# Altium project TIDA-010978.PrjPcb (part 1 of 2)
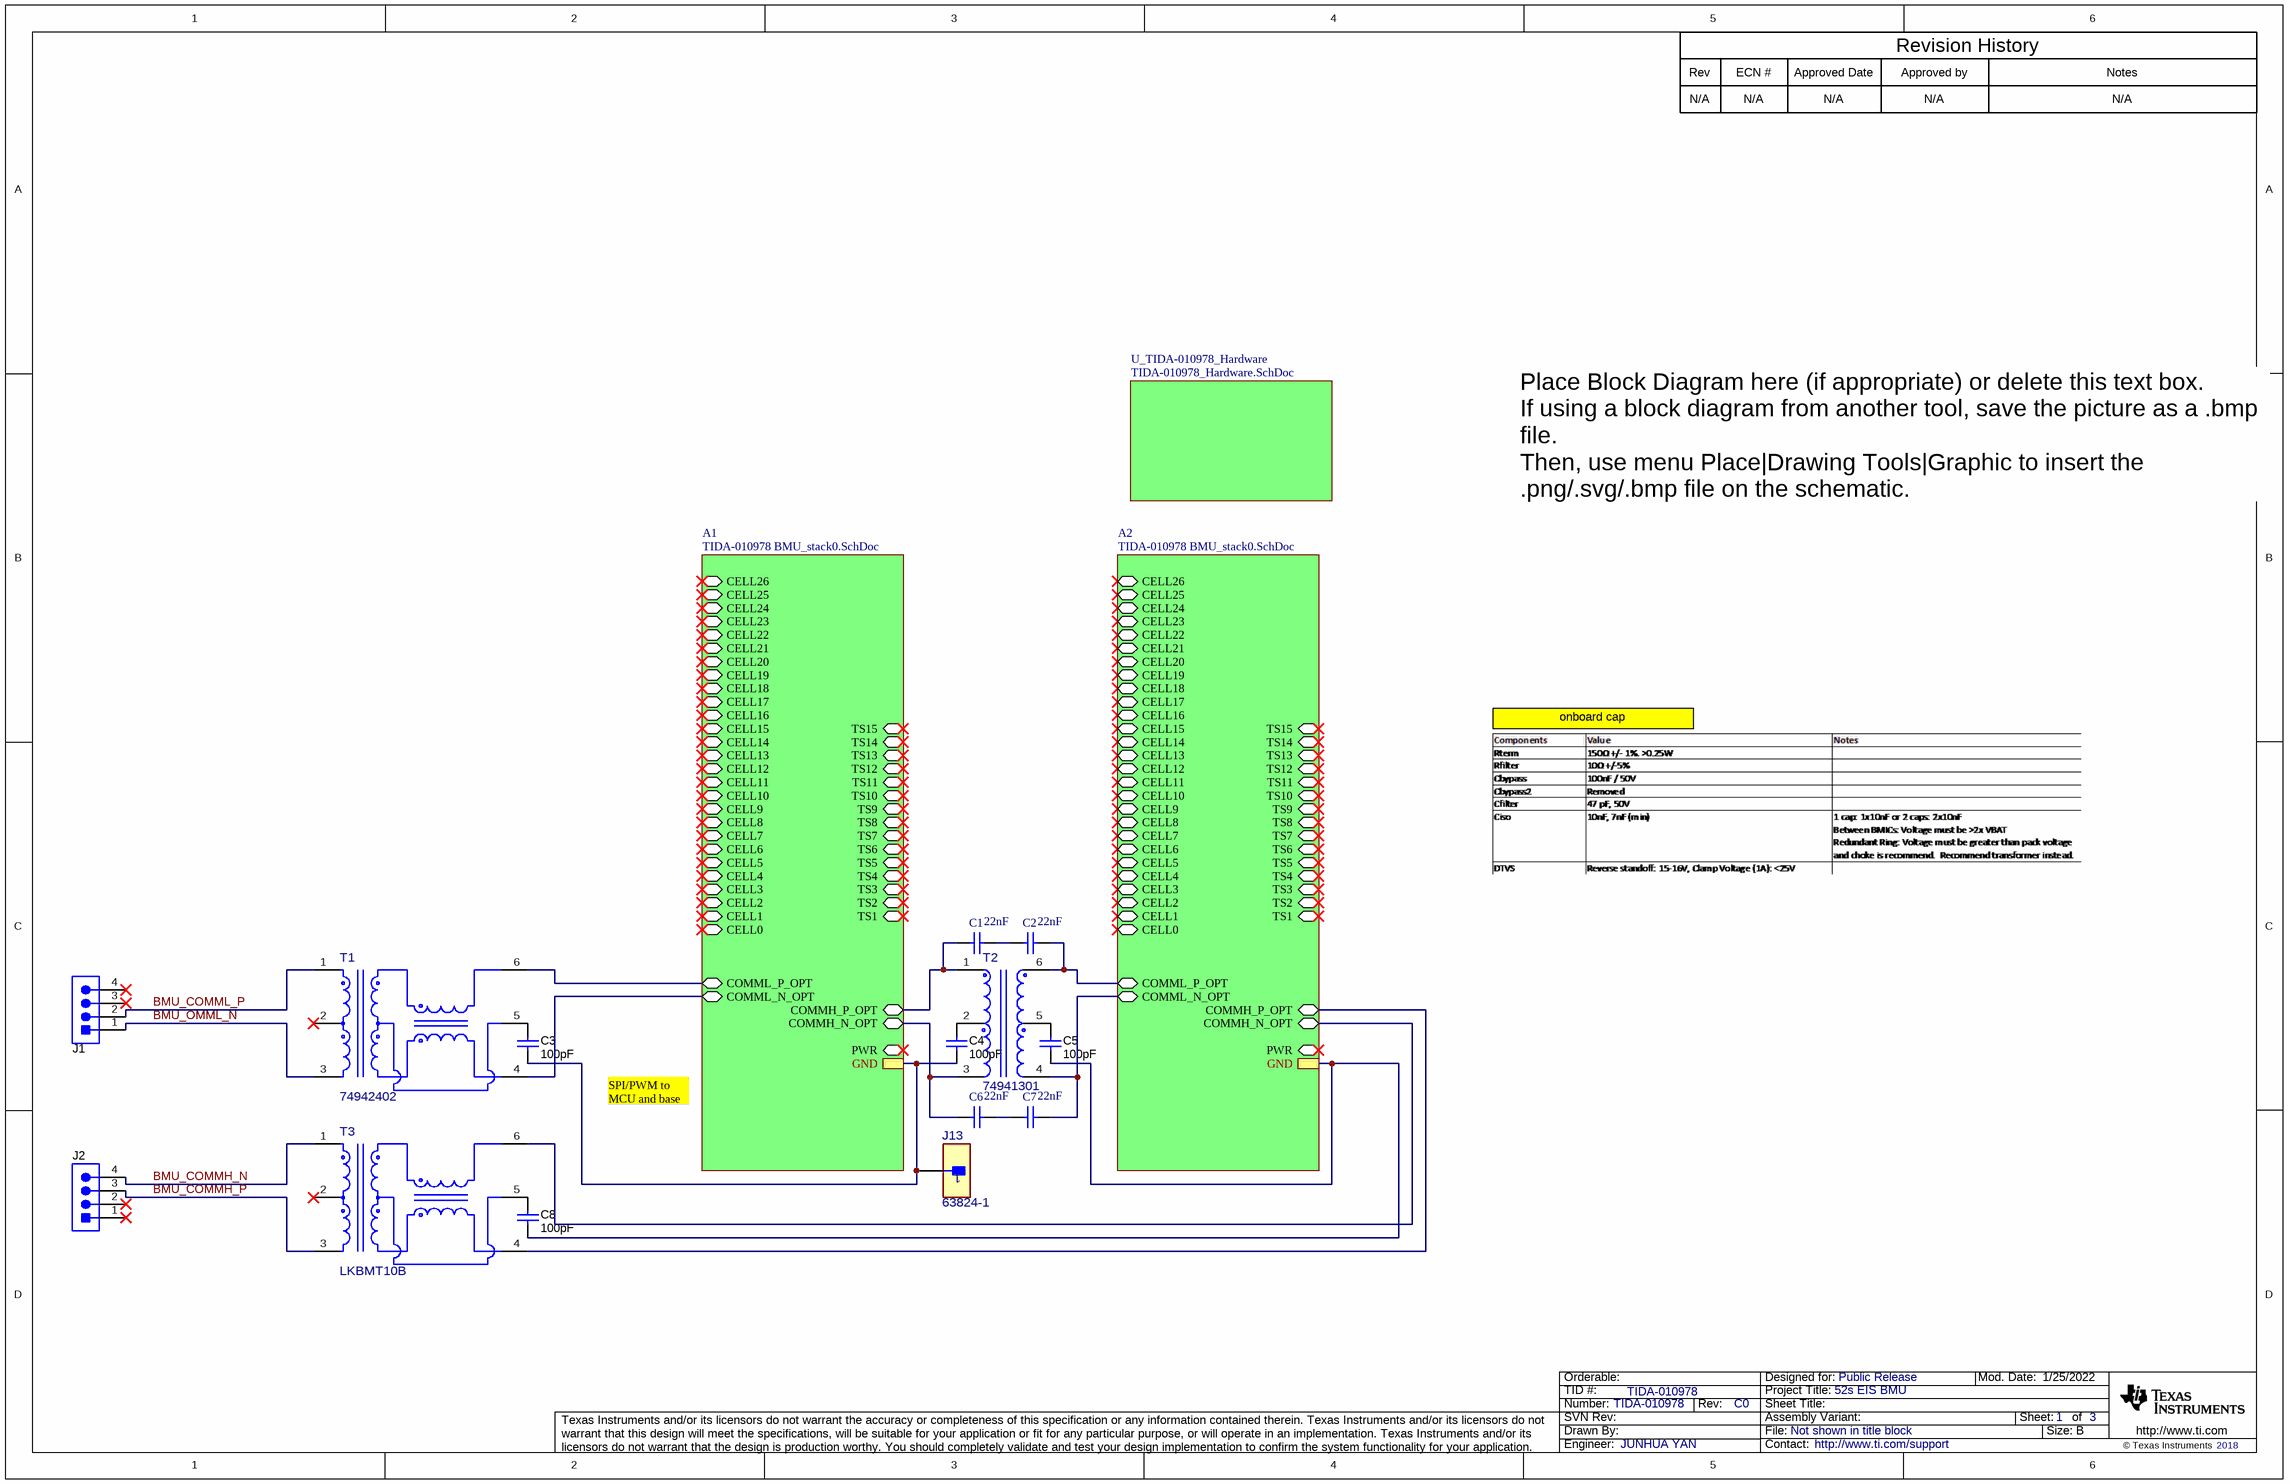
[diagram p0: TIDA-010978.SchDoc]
TID: TIDA-010978; TechSupport: http://www.ti.com/support; SCH_Rev: C0; PRJ_Title: 52s EIS BMU; PRJ_Number: TIDA-010978; PRJ_Engineer: JUNHUA YAN; PRJ_Customer: Public Release; PCB_Rev: C0; PCB_Layout: JUNHUA YAN; CopyrightYear: 2018
3 sheets, 866 parts. Net scope: hierarchical (ports join the sheet entries above them; power ports are global).
Board file: TIDA-010978.PcbDoc
Sheets:
  TIDA-010978.SchDoc
    A1 = TIDA-010978 BMU_stack0.SchDoc
    A2 = TIDA-010978 BMU_stack0.SchDoc
    U_TIDA-010978_Hardware = TIDA-010978_Hardware.SchDoc

## Sheet TIDA-010978.SchDoc
size 431 x 279 mm; Date: Not shown in title block; ApprovedBy: Not shown in title block; CheckedBy: Not shown in title block; Author: Not shown in title block; CompanyName: Not shown in title block; Engineer: Not shown in title block; Organization: Not shown in title block; Address1: Not shown in title block; Address2: Not shown in title block; Address3: Not shown in title block; Address4: Not shown in title block; DocumentNumber: 1; Revision: Use project parameter SCH_Rev; SheetNumber: 1; SheetTotal: 3; PageSetup: Record=PageOptions¦CenterHorizontal=True¦CenterVertical=True¦PrintScale=1.00¦XCorrection=1.00¦YCorrection=1.00¦PrintKind=0¦BorderSize=5000000¦LeftOffset=0¦BottomOffset=0¦Orientation=2¦PaperLength=1000¦PaperWidth=1000¦Scale=100¦PaperSource=15¦PrintQuality=600¦MediaType=1¦DitherType=10¦PaperKind=Letter¦PrintScaleMode=1

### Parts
C1  Capacitance: 22nF  [WCAP-CSMH_0805_L2W1.25H1.25]  (hidden comment: 885342207006)
C2  Capacitance: 22nF  [WCAP-CSMH_0805_L2W1.25H1.25]  (hidden comment: 885342207006)
C3  ValueDisplayed: 100pF  [0603]  (hidden comment: GCM1885C1H101JA16J)
C4  ValueDisplayed: 100pF  [0603]  (hidden comment: GCM1885C1H101JA16J)
C5  ValueDisplayed: 100pF  [0603]  (hidden comment: GCM1885C1H101JA16J)
C6  Capacitance: 22nF  [WCAP-CSMH_0805_L2W1.25H1.25]  (hidden comment: 885342207006)
C7  Capacitance: 22nF  [WCAP-CSMH_0805_L2W1.25H1.25]  (hidden comment: 885342207006)
C8  ValueDisplayed: 100pF  [0603]  (hidden comment: GCM1885C1H101JA16J)
J1  70551-0038  [Molex_70551-0038]  (value not drawn)
J2  70551-0038  [Molex_70551-0038]  (value not drawn)
J13  63824-1  [FP-63824-1_CONN_7MM92_3MM11-MFG]
T1  74942402  [FP-LKBMT10B_SMT_XFRMR_27MM9_12MM5-MFG]
T2  74941301  [FP-HMU1228NL_SMT_TRANSFORMER_8MM89_10MM09-MFG]
T3  LKBMT10B  [FP-LKBMT10B_SMT_XFRMR_27MM9_12MM5-MFG]

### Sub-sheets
A1 = TIDA-010978 BMU_stack0.SchDoc: PWR (bidir), CELL9 (bidir), CELL10 (bidir), CELL11 (bidir), CELL12 (bidir), CELL13 (bidir), CELL14 (bidir), CELL15 (bidir), CELL16 (bidir), CELL8 (bidir), CELL17 (bidir), CELL18 (bidir), CELL1 (bidir), CELL2 (bidir), CELL3 (bidir), CELL4 (bidir), CELL5 (bidir), CELL6 (bidir), CELL7 (bidir), CELL0 (bidir), COMML_N_OPT (bidir), COMML_P_OPT (bidir), COMMH_N_OPT (bidir), COMMH_P_OPT (bidir), GND, CELL19 (bidir), CELL20 (bidir), CELL21 (bidir), CELL22 (bidir), CELL23 (bidir), CELL24 (bidir), CELL25 (bidir), CELL26 (bidir), TS8 (bidir), TS6 (bidir), TS15 (bidir), TS14 (bidir), TS13 (bidir), TS12 (bidir), TS11 (bidir), TS10 (bidir), TS9 (bidir), TS7 (bidir), TS4 (bidir), TS2 (bidir), TS5 (bidir), TS3 (bidir), TS1 (bidir)
A2 = TIDA-010978 BMU_stack0.SchDoc: PWR (bidir), CELL9 (bidir), CELL10 (bidir), CELL11 (bidir), CELL12 (bidir), CELL13 (bidir), CELL14 (bidir), CELL15 (bidir), CELL16 (bidir), CELL8 (bidir), CELL17 (bidir), CELL18 (bidir), CELL1 (bidir), CELL2 (bidir), CELL3 (bidir), CELL4 (bidir), CELL5 (bidir), CELL6 (bidir), CELL7 (bidir), CELL0 (bidir), COMML_N_OPT (bidir), COMML_P_OPT (bidir), COMMH_N_OPT (bidir), COMMH_P_OPT (bidir), GND, CELL19 (bidir), CELL20 (bidir), CELL21 (bidir), CELL22 (bidir), CELL23 (bidir), CELL24 (bidir), CELL25 (bidir), CELL26 (bidir), TS8 (bidir), TS6 (bidir), TS15 (bidir), TS14 (bidir), TS13 (bidir), TS12 (bidir), TS11 (bidir), TS10 (bidir), TS9 (bidir), TS7 (bidir), TS4 (bidir), TS2 (bidir), TS5 (bidir), TS3 (bidir), TS1 (bidir)  | J7_A2@2.Installed: False
U_TIDA-010978_Hardware = TIDA-010978_Hardware.SchDoc: no entries

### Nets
GND: C3.1 C4.1 C5.1 C8.1 J13.1 ; sheet A1/GND, sheet A2/GND
BMU_COMMH_N: J2.4 T3.1
BMU_COMMH_P: J2.3 T3.3
BMU_COMML_P: J1.2 T1.1
BMU_OMML_N: J1.1 T1.3
COMMH_N_OPT: C6.1 T2.3(TD-) ; sheet A1/COMMH_N_OPT
COMMH_N_OPT: T3.6 ; sheet A2/COMMH_N_OPT  [a separate net that carries the same name]
COMMH_P_OPT: C1.1 T2.1(TD+) ; sheet A1/COMMH_P_OPT
COMMH_P_OPT: T3.4 ; sheet A2/COMMH_P_OPT  [a separate net that carries the same name]
COMML_N_OPT: C7.2 T2.4(TX-) ; sheet A2/COMML_N_OPT
COMML_N_OPT: T1.4 ; sheet A1/COMML_N_OPT  [a separate net that carries the same name]
COMML_P_OPT: C2.2 T2.6(TX+) ; sheet A2/COMML_P_OPT
COMML_P_OPT: T1.6 ; sheet A1/COMML_P_OPT  [a separate net that carries the same name]
NetC1_2: C1.2 C2.1
NetC3_2: C3.2 T1.5
NetC4_2: C4.2 T2.2(TCT)
NetC5_2: C5.2 T2.5(CMT)
NetC6_2: C6.2 C7.1
NetC8_2: C8.2 T3.5

Not connected (* = marked no-connect by the designer): J1 3* 4*; J2 1* 2*; T1 2*; T3 2*

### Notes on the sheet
- Rev
- N/A
- ECN #
- Approved Date
- Approved by
- Revision History
- Notes
- Place Block Diagram here (if appropriate) or delete this text box.
  If using a block diagram from another tool, save the picture as a .bmp file.
  Then, use menu Place|Drawing Tools|Graphic to insert the .png/.svg/.bmp file on the schematic.
- onboard cap
- SPI/PWM to MCU and base

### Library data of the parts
C1 C2 C6 C7 = CMP-03913-89205736-1: 885342207006 Cap Cer 0.022UF 200V X7R 0805; Manufacturer: Wurth Elektronik; Insulation Resistance: 4.545GΩ
C3-C5 C8 = CMP-0750041-1: CAP, CERM, 100 pF, 50 V,+/- 5%, C0G/NP0, AEC-Q200 Grade 1, 0603; Manufacturer: MuRata; TaMin_C: -55°C; Polarized: N; SizeAreaWB_mm2: 4.68; U/M: EA; Value: 100pF; TaMax_C: 125°C; SizeZ_mm: 1; SizeX_mm: 1.6; SizeY_mm: 0.8; Value2: 50V; SizeArea_mm2: 1.28; AEC Qualified: Y; AEC Category: Q200
J1 J2 = CMP-0055239-1: Header(shrouded), 2.54mm, 4x1, R/A, Gold, TH; Manufacturer: Molex; CNHeader: FALSE; Current_A: 3A; Green_Lifecycle: Active; Shrouded: Y; Gender: Male; Green_REACh: Passed; Voltage_V: 250V; Row_Count: 1; Pitch_mm: 2.54
J13 = CMP-0089624-1: 0.250" (6.35mm) Quick Connect Male  Solder Connector Non-Insulated; Manufacturer: TE Connectivity; SizeZ_mm: 10.71mm; Conn Orientation: Straight; AEC Qualified: No; Import Ts: 1521847382; ContactFinish: Tin,Nickel; Current_A: 20A; Ciiva Ids: 766930
T1 = CMP-0122349-1: SMD BMS Transformer; Manufacturer: Wurth Elektronik; Part Number: LKBMT10B; DCR_ohm: 0.8; Ind_H: 300µH; Ns1toNp: 1:1; Rsec1_ohm: 1; SizeZ_mm: 9.5mm; AEC Qualified: Yes; AEC Grade: Grade 1; Insertion Loss: -0.5dB; Return Loss: -20dB; Voltage_Isolation_Vrms: 5000VDC
T2 = CMP-0086619-1: BMS TRANSFORMER; Manufacturer: Wurth Elektronik; Ns1toNp: 1:1; Ind_H: 150µH; SizeZ_mm: 6.85mm; AEC Grade: Grade 1; AEC Qualified: Yes
T3 = CMP-0122349-1: SMD BMS Transformer; Manufacturer: LineKey Technology; DCR_ohm: 0.8; Ind_H: 300µH; Ns1toNp: 1:1; Rsec1_ohm: 1; SizeZ_mm: 9.5mm; AEC Qualified: Yes; AEC Grade: Grade 1; Insertion Loss: -0.5dB; Return Loss: -20dB; Voltage_Isolation_Vrms: 5000VDC

## Sheet TIDA-010978 BMU_stack0.SchDoc
size 558 x 431 mm; Date: Not shown in title block; ApprovedBy: Not shown in title block; CheckedBy: Not shown in title block; Author: Not shown in title block; CompanyName: Not shown in title block; Engineer: Not shown in title block; Organization: Not shown in title block; Address1: Not shown in title block; Address2: Not shown in title block; Address3: Not shown in title block; Address4: Not shown in title block; DocumentNumber: 2; Revision: Use project parameter SCH_Rev; SheetNumber: 2; SheetTotal: 3; PageSetup: Record=PageOptions¦CenterHorizontal=True¦CenterVertical=True¦PrintScale=1.00¦XCorrection=1.00¦YCorrection=1.00¦PrintKind=0¦BorderSize=5000000¦LeftOffset=0¦BottomOffset=0¦Orientation=2¦PaperLength=1000¦PaperWidth=1000¦Scale=100¦PaperSource=15¦PrintQuality=600¦MediaType=1¦DitherType=10¦PaperKind=Letter¦PrintScaleMode=1
Used 2 times, as channels A1, A2. Parts and nets are listed once, with the designators drawn on the sheet.
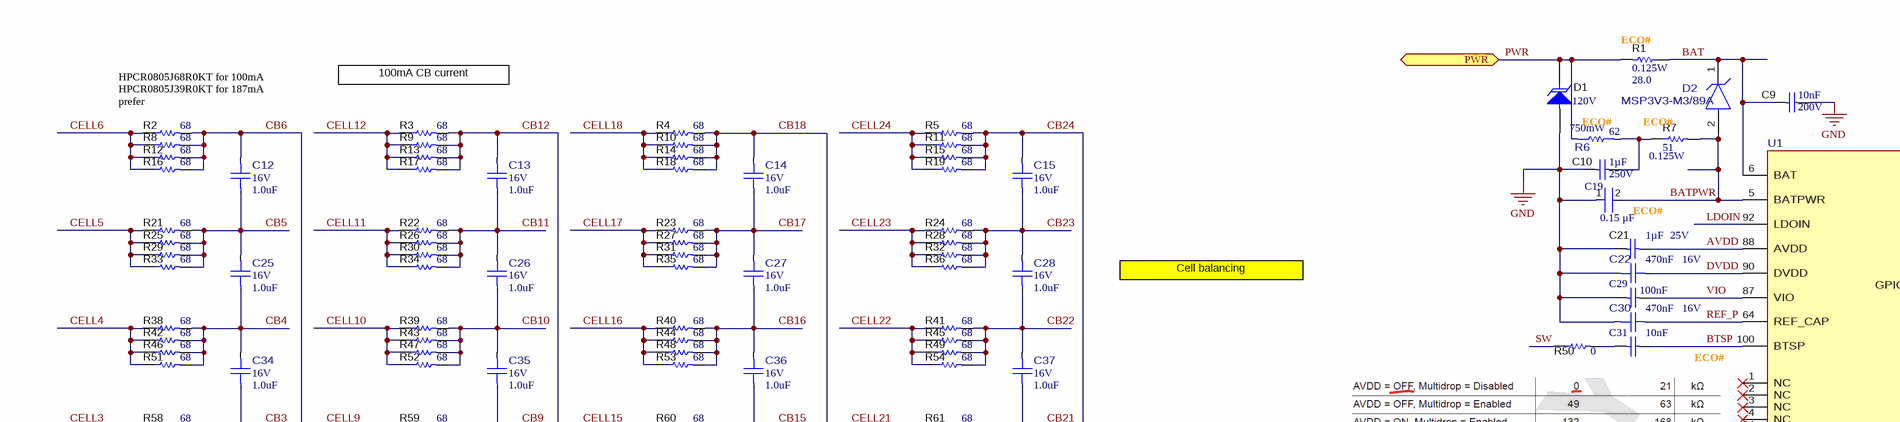
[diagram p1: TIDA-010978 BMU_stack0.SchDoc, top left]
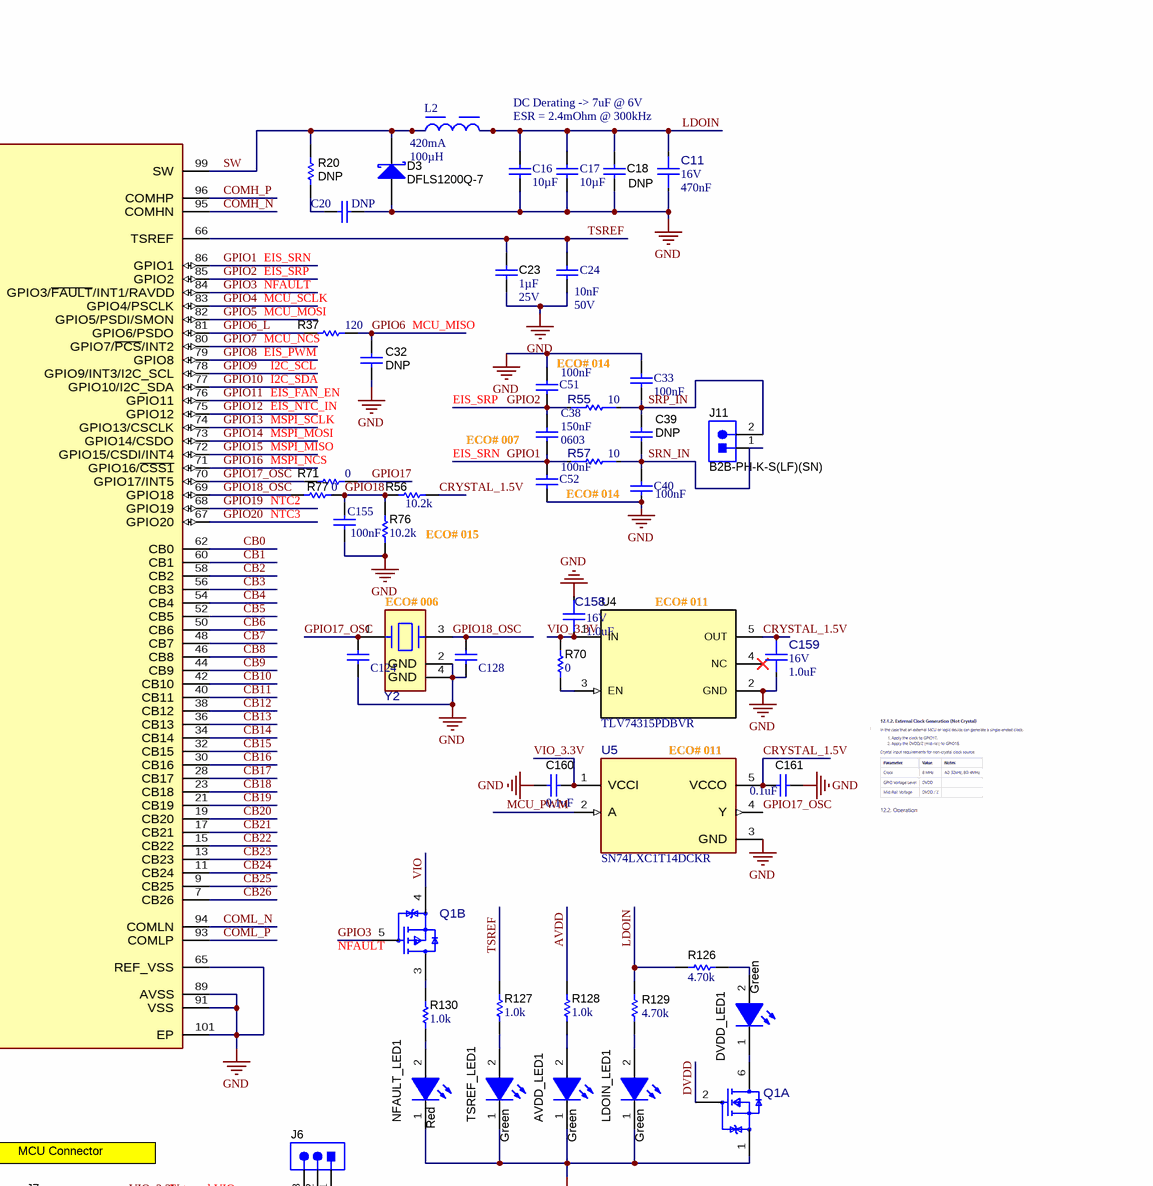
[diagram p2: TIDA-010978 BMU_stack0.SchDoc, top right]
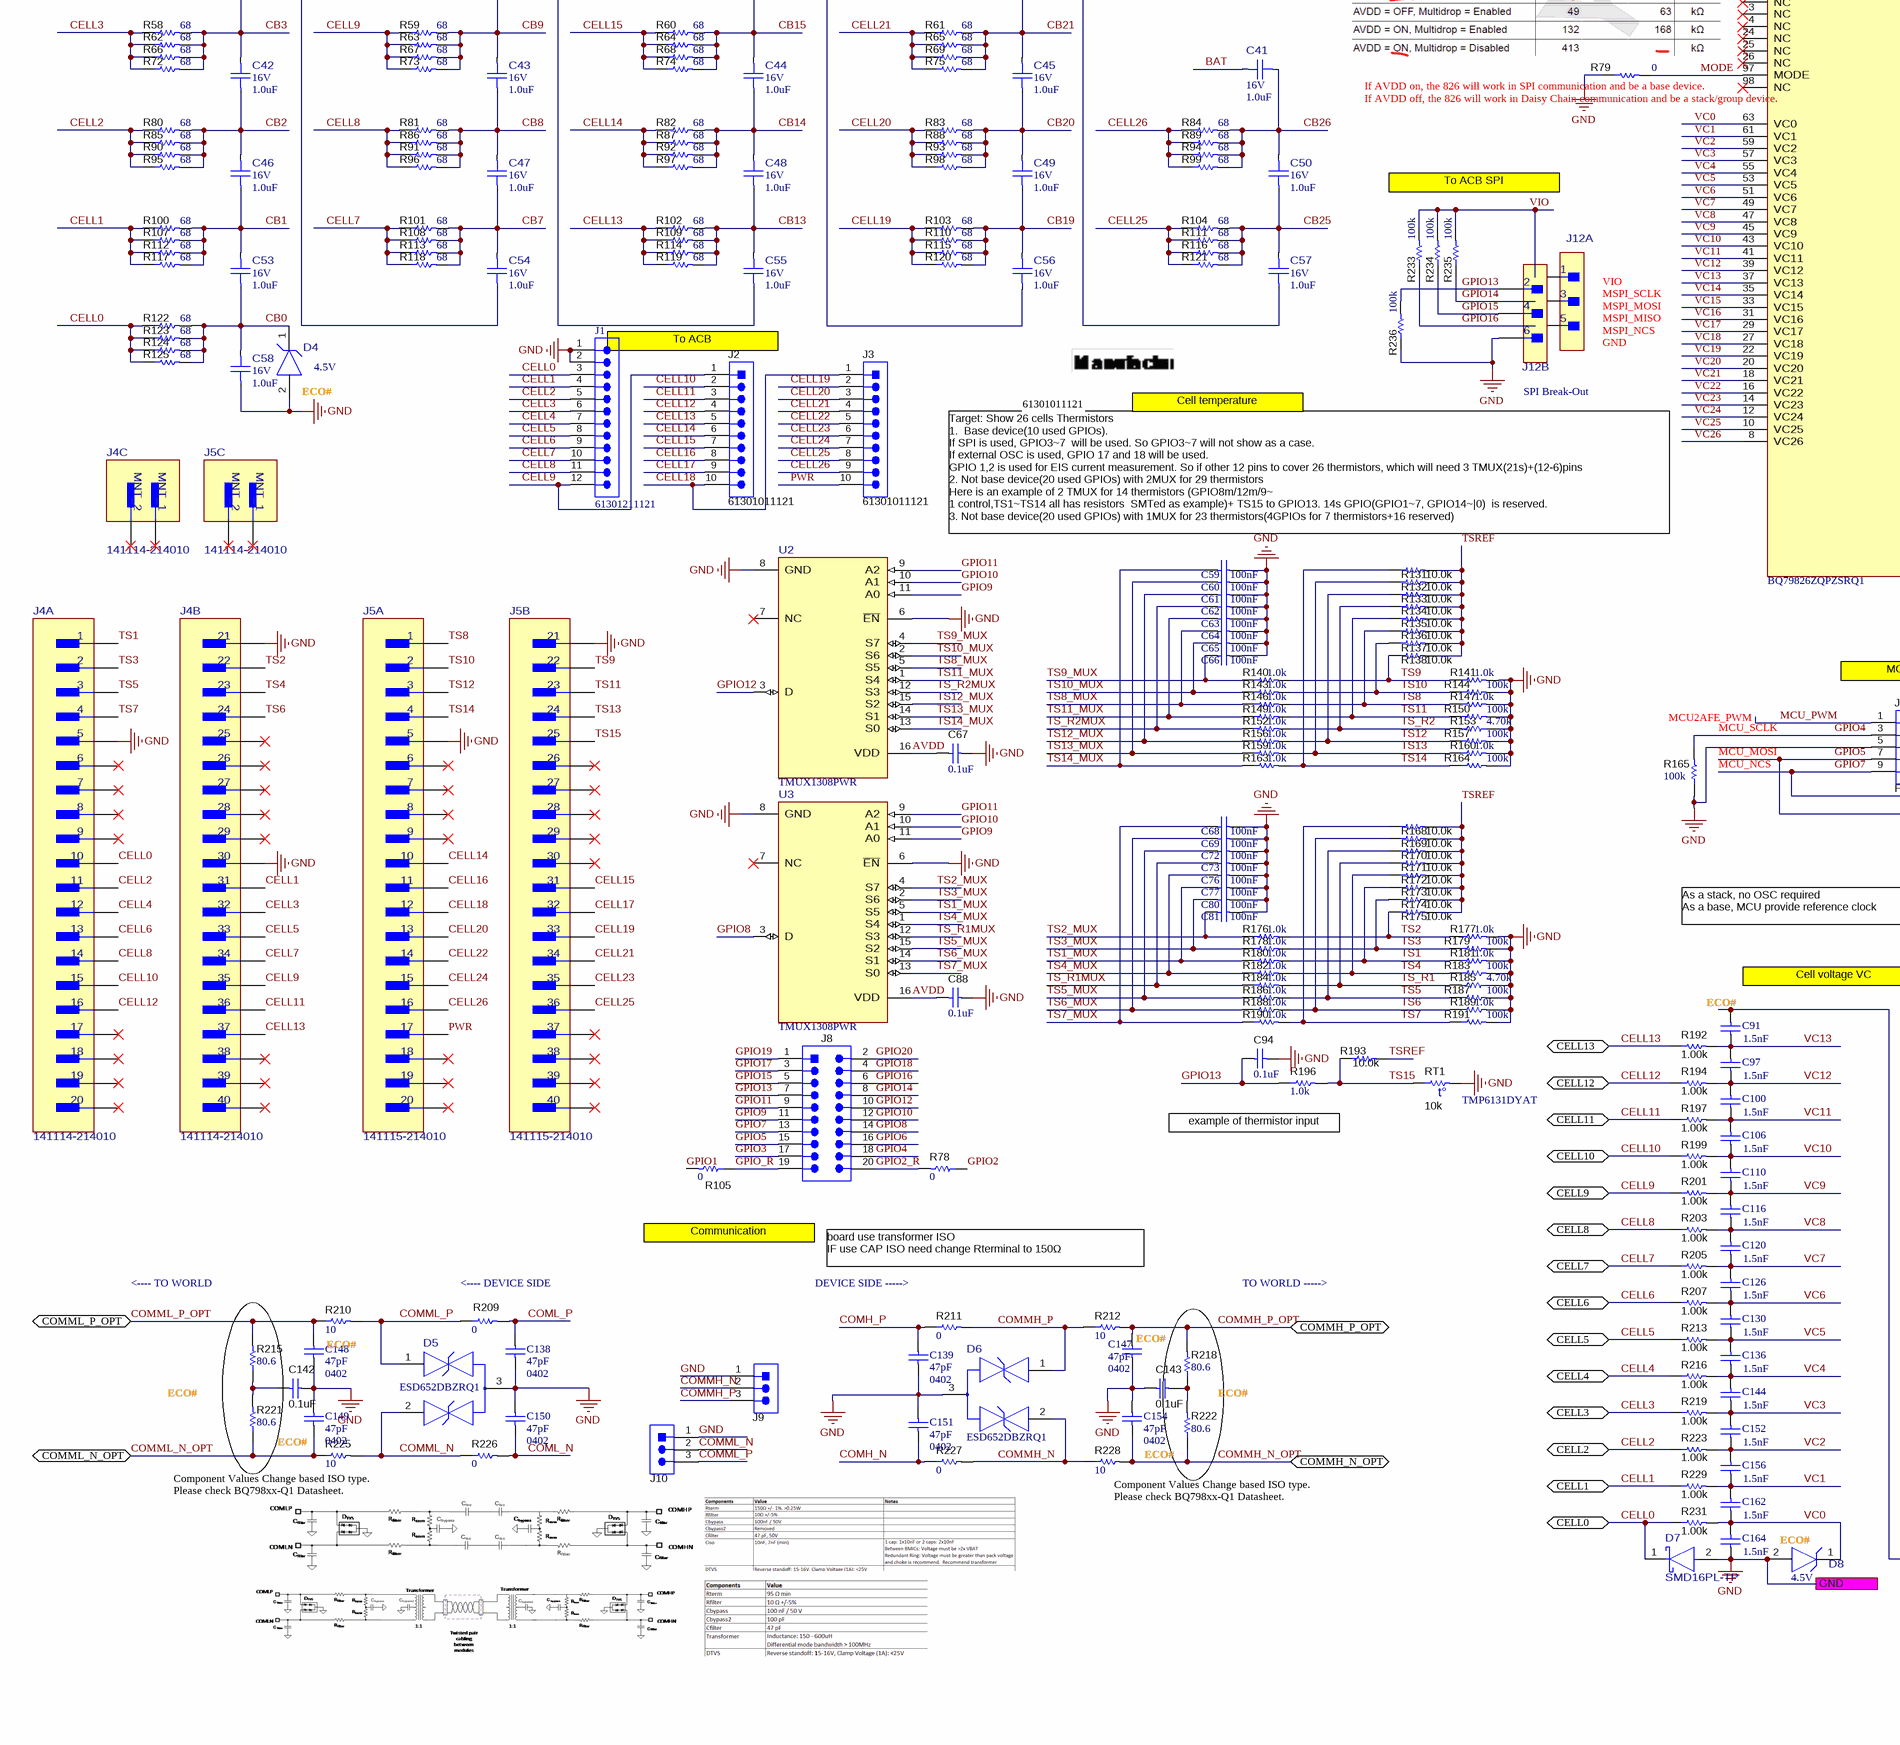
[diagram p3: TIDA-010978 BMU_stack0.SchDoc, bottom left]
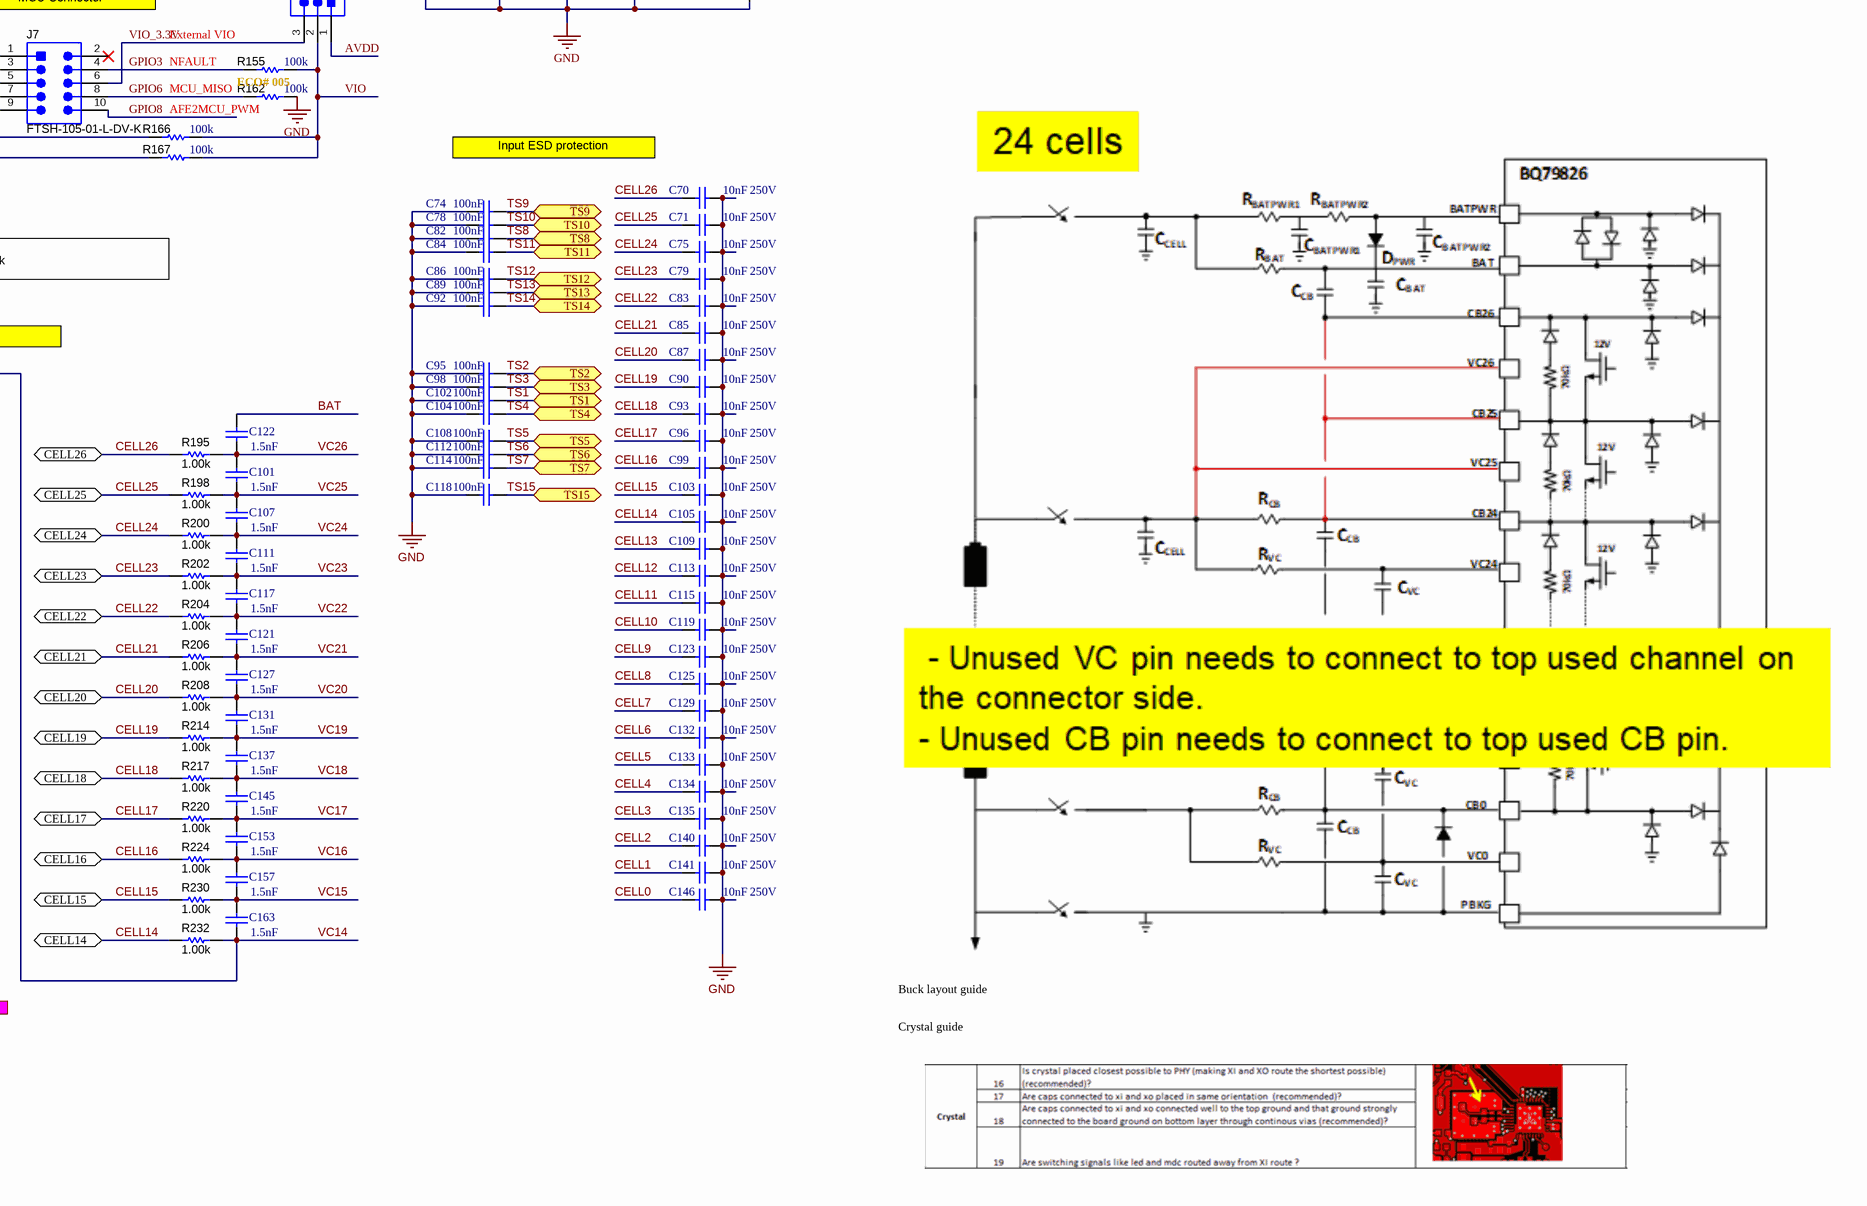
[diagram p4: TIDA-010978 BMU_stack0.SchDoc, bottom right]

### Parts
AVDD_LED1  value Green  [WL-SMCW_GREEN]  (hidden comment: 150060GS75000)
C9  Cap_F: 10nF  VDC_V: 200V  [0603]  (hidden comment: C0603C103K2RACTU)
C10  ValueDisplayed: 1µF  VDC_V: 250V  [2220_280]  (hidden comment: CGA9N3X7R2E105K230KE)
C11  VDC_V: 16V  Cap_F: 470nF  [FP-885012206050_0603-MFG]  (hidden comment: 885012206050)
C12  VDC_V: 16V  ValueDisplayed: 1.0uF  [FP-GRM155C81C105KE11D_0402-MFG]  (hidden comment: GRM155C81C105KE11D)
C13  VDC_V: 16V  ValueDisplayed: 1.0uF  [FP-GRM155C81C105KE11D_0402-MFG]  (hidden comment: GRM155C81C105KE11D)
C14  VDC_V: 16V  ValueDisplayed: 1.0uF  [FP-GRM155C81C105KE11D_0402-MFG]  (hidden comment: GRM155C81C105KE11D)
C15  VDC_V: 16V  ValueDisplayed: 1.0uF  [FP-GRM155C81C105KE11D_0402-MFG]  (hidden comment: GRM155C81C105KE11D)
C16  Capacitance: 10µF  [WCAP-CSGP_0805_L2W1.25H1.25]  (hidden comment: 885012107014)
C17  Capacitance: 10µF  [WCAP-CSGP_0805_L2W1.25H1.25]  (hidden comment: 885012107014)
C18  DNP  [0805_HV]
C19  Capacitance: 0.15 μF  [FP-C1206C-EB-MFG]  (hidden comment: C1206C154KARACAUTO)
C20  DNP  [WCAP-CSMH_0603_L1.6W0.8H0.8_Reflow]
C21  Cap_F: 1µF  VDC_V: 25V  [0603]  (hidden comment: 885012206076)
C22  VDC_V: 16V  Cap_F: 470nF  [FP-885012206050_0603-MFG]  (hidden comment: 885012206050)
C23  Cap_F: 1µF  VDC_V: 25V  [0603]  (hidden comment: 885012206076)
C24  Cap_F: 10nF  Rated Voltage (DC): 50V  [WCAP-CSGP_0603_L1.6W0.8H0.8_Reflow]  (hidden comment: 885012206089)
C25  VDC_V: 16V  ValueDisplayed: 1.0uF  [FP-GRM155C81C105KE11D_0402-MFG]  (hidden comment: GRM155C81C105KE11D)
C26  VDC_V: 16V  ValueDisplayed: 1.0uF  [FP-GRM155C81C105KE11D_0402-MFG]  (hidden comment: GRM155C81C105KE11D)
C27  VDC_V: 16V  ValueDisplayed: 1.0uF  [FP-GRM155C81C105KE11D_0402-MFG]  (hidden comment: GRM155C81C105KE11D)
C28  VDC_V: 16V  ValueDisplayed: 1.0uF  [FP-GRM155C81C105KE11D_0402-MFG]  (hidden comment: GRM155C81C105KE11D)
C29  Capacitance: 100nF  [WCAP-CSGP_0402_L1W0.5H0.5]  (hidden comment: 885012205092)
C30  VDC_V: 16V  Cap_F: 470nF  [FP-885012206050_0603-MFG]  (hidden comment: 885012206050)
C31  Cap_F: 10nF  [WCAP-CSGP_0402_L1W0.5H0.5]  (hidden comment: 885012205067)
C32  DNP  [0402]
C33  Capacitance: 100nF  [WCAP-CSGP_0402_L1W0.5H0.5]  (hidden comment: 885012205092)
C34  VDC_V: 16V  ValueDisplayed: 1.0uF  [FP-GRM155C81C105KE11D_0402-MFG]  (hidden comment: GRM155C81C105KE11D)
C35  VDC_V: 16V  ValueDisplayed: 1.0uF  [FP-GRM155C81C105KE11D_0402-MFG]  (hidden comment: GRM155C81C105KE11D)
C36  VDC_V: 16V  ValueDisplayed: 1.0uF  [FP-GRM155C81C105KE11D_0402-MFG]  (hidden comment: GRM155C81C105KE11D)
C37  VDC_V: 16V  ValueDisplayed: 1.0uF  [FP-GRM155C81C105KE11D_0402-MFG]  (hidden comment: GRM155C81C105KE11D)
C38  Cap_F: 150nF  Case/Size Code: 0603  [WCAP-CSGP_0603_L1.6W0.8H0.8_Reflow]  (hidden comment: 885012206072)
C39  DNP  [0603]
C40  Capacitance: 100nF  [WCAP-CSGP_0402_L1W0.5H0.5]  (hidden comment: 885012205092)
C41  VDC_V: 16V  ValueDisplayed: 1.0uF  [FP-GRM155C81C105KE11D_0402-MFG]  (hidden comment: GRM155C81C105KE11D)
C42  VDC_V: 16V  ValueDisplayed: 1.0uF  [FP-GRM155C81C105KE11D_0402-MFG]  (hidden comment: GRM155C81C105KE11D)
C43  VDC_V: 16V  ValueDisplayed: 1.0uF  [FP-GRM155C81C105KE11D_0402-MFG]  (hidden comment: GRM155C81C105KE11D)
C44  VDC_V: 16V  ValueDisplayed: 1.0uF  [FP-GRM155C81C105KE11D_0402-MFG]  (hidden comment: GRM155C81C105KE11D)
C45  VDC_V: 16V  ValueDisplayed: 1.0uF  [FP-GRM155C81C105KE11D_0402-MFG]  (hidden comment: GRM155C81C105KE11D)
C46  VDC_V: 16V  ValueDisplayed: 1.0uF  [FP-GRM155C81C105KE11D_0402-MFG]  (hidden comment: GRM155C81C105KE11D)
C47  VDC_V: 16V  ValueDisplayed: 1.0uF  [FP-GRM155C81C105KE11D_0402-MFG]  (hidden comment: GRM155C81C105KE11D)
C48  VDC_V: 16V  ValueDisplayed: 1.0uF  [FP-GRM155C81C105KE11D_0402-MFG]  (hidden comment: GRM155C81C105KE11D)
C49  VDC_V: 16V  ValueDisplayed: 1.0uF  [FP-GRM155C81C105KE11D_0402-MFG]  (hidden comment: GRM155C81C105KE11D)
C50  VDC_V: 16V  ValueDisplayed: 1.0uF  [FP-GRM155C81C105KE11D_0402-MFG]  (hidden comment: GRM155C81C105KE11D)
C51  Capacitance: 100nF  [WCAP-CSGP_0402_L1W0.5H0.5]  (hidden comment: 885012205092)
C52  Capacitance: 100nF  [WCAP-CSGP_0402_L1W0.5H0.5]  (hidden comment: 885012205092)
C53  VDC_V: 16V  ValueDisplayed: 1.0uF  [FP-GRM155C81C105KE11D_0402-MFG]  (hidden comment: GRM155C81C105KE11D)
C54  VDC_V: 16V  ValueDisplayed: 1.0uF  [FP-GRM155C81C105KE11D_0402-MFG]  (hidden comment: GRM155C81C105KE11D)
C55  VDC_V: 16V  ValueDisplayed: 1.0uF  [FP-GRM155C81C105KE11D_0402-MFG]  (hidden comment: GRM155C81C105KE11D)
C56  VDC_V: 16V  ValueDisplayed: 1.0uF  [FP-GRM155C81C105KE11D_0402-MFG]  (hidden comment: GRM155C81C105KE11D)
C57  VDC_V: 16V  ValueDisplayed: 1.0uF  [FP-GRM155C81C105KE11D_0402-MFG]  (hidden comment: GRM155C81C105KE11D)
C58  VDC_V: 16V  ValueDisplayed: 1.0uF  [FP-GRM155C81C105KE11D_0402-MFG]  (hidden comment: GRM155C81C105KE11D)
C59  Cap_F: 100nF  [WCAP-CSGP_0402_L1W0.5H0.5]  (hidden comment: 885012205086)
C60  Cap_F: 100nF  [WCAP-CSGP_0402_L1W0.5H0.5]  (hidden comment: 885012205086)
C61  Cap_F: 100nF  [WCAP-CSGP_0402_L1W0.5H0.5]  (hidden comment: 885012205086)
C62  Cap_F: 100nF  [WCAP-CSGP_0402_L1W0.5H0.5]  (hidden comment: 885012205086)
C63  Cap_F: 100nF  [WCAP-CSGP_0402_L1W0.5H0.5]  (hidden comment: 885012205086)
C64  Cap_F: 100nF  [WCAP-CSGP_0402_L1W0.5H0.5]  (hidden comment: 885012205086)
C65  Cap_F: 100nF  [WCAP-CSGP_0402_L1W0.5H0.5]  (hidden comment: 885012205086)
C66  Cap_F: 100nF  [WCAP-CSGP_0402_L1W0.5H0.5]  (hidden comment: 885012205086)
C67  ValueDisplayed: 0.1uF  [0402]  (hidden comment: GCM155R71H104KE02D)
C68  Cap_F: 100nF  [WCAP-CSGP_0402_L1W0.5H0.5]  (hidden comment: 885012205086)
C69  Cap_F: 100nF  [WCAP-CSGP_0402_L1W0.5H0.5]  (hidden comment: 885012205086)
C70  Cap_F: 10nF  Rated Voltage (DC): 250V  [WCAP-CSMH_0603_L1.6W0.8H0.8_Reflow]  (hidden comment: 885342206006)
C71  Cap_F: 10nF  Rated Voltage (DC): 250V  [WCAP-CSMH_0603_L1.6W0.8H0.8_Reflow]  (hidden comment: 885342206006)
C72  Cap_F: 100nF  [WCAP-CSGP_0402_L1W0.5H0.5]  (hidden comment: 885012205086)
C73  Cap_F: 100nF  [WCAP-CSGP_0402_L1W0.5H0.5]  (hidden comment: 885012205086)
C74  Cap_F: 100nF  [WCAP-CSGP_0402_L1W0.5H0.5]  (hidden comment: 885012205085R)
C75  Cap_F: 10nF  Rated Voltage (DC): 250V  [WCAP-CSMH_0603_L1.6W0.8H0.8_Reflow]  (hidden comment: 885342206006)
C76  Cap_F: 100nF  [WCAP-CSGP_0402_L1W0.5H0.5]  (hidden comment: 885012205086)
C77  Cap_F: 100nF  [WCAP-CSGP_0402_L1W0.5H0.5]  (hidden comment: 885012205086)
C78  Cap_F: 100nF  [WCAP-CSGP_0402_L1W0.5H0.5]  (hidden comment: 885012205085R)
C79  Cap_F: 10nF  Rated Voltage (DC): 250V  [WCAP-CSMH_0603_L1.6W0.8H0.8_Reflow]  (hidden comment: 885342206006)
C80  Cap_F: 100nF  [WCAP-CSGP_0402_L1W0.5H0.5]  (hidden comment: 885012205086)
C81  Cap_F: 100nF  [WCAP-CSGP_0402_L1W0.5H0.5]  (hidden comment: 885012205086)
C82  Cap_F: 100nF  [WCAP-CSGP_0402_L1W0.5H0.5]  (hidden comment: 885012205085R)
C83  Cap_F: 10nF  Rated Voltage (DC): 250V  [WCAP-CSMH_0603_L1.6W0.8H0.8_Reflow]  (hidden comment: 885342206006)
C84  Cap_F: 100nF  [WCAP-CSGP_0402_L1W0.5H0.5]  (hidden comment: 885012205085R)
C85  Cap_F: 10nF  Rated Voltage (DC): 250V  [WCAP-CSMH_0603_L1.6W0.8H0.8_Reflow]  (hidden comment: 885342206006)
C86  Cap_F: 100nF  [WCAP-CSGP_0402_L1W0.5H0.5]  (hidden comment: 885012205085R)
C87  Cap_F: 10nF  Rated Voltage (DC): 250V  [WCAP-CSMH_0603_L1.6W0.8H0.8_Reflow]  (hidden comment: 885342206006)
C88  ValueDisplayed: 0.1uF  [0402]  (hidden comment: GCM155R71H104KE02D)
C89  Cap_F: 100nF  [WCAP-CSGP_0402_L1W0.5H0.5]  (hidden comment: 885012205085R)
C90  Cap_F: 10nF  Rated Voltage (DC): 250V  [WCAP-CSMH_0603_L1.6W0.8H0.8_Reflow]  (hidden comment: 885342206006)
C91  Cap_F: 1.5nF  [WCAP-CSGP_0402_L1W0.5H0.5]  (hidden comment: 885012205062)
C92  Cap_F: 100nF  [WCAP-CSGP_0402_L1W0.5H0.5]  (hidden comment: 885012205085R)
C93  Cap_F: 10nF  Rated Voltage (DC): 250V  [WCAP-CSMH_0603_L1.6W0.8H0.8_Reflow]  (hidden comment: 885342206006)
C94  ValueDisplayed: 0.1uF  [0402]  (hidden comment: GCM155R71H104KE02D)
C95  Cap_F: 100nF  [WCAP-CSGP_0402_L1W0.5H0.5]  (hidden comment: 885012205085R)
C96  Cap_F: 10nF  Rated Voltage (DC): 250V  [WCAP-CSMH_0603_L1.6W0.8H0.8_Reflow]  (hidden comment: 885342206006)
C97  Cap_F: 1.5nF  [WCAP-CSGP_0402_L1W0.5H0.5]  (hidden comment: 885012205062)
C98  Cap_F: 100nF  [WCAP-CSGP_0402_L1W0.5H0.5]  (hidden comment: 885012205085R)
C99  Cap_F: 10nF  Rated Voltage (DC): 250V  [WCAP-CSMH_0603_L1.6W0.8H0.8_Reflow]  (hidden comment: 885342206006)
C100  Cap_F: 1.5nF  [WCAP-CSGP_0402_L1W0.5H0.5]  (hidden comment: 885012205062)
C101  Cap_F: 1.5nF  [WCAP-CSGP_0402_L1W0.5H0.5]  (hidden comment: 885012205062)
C102  Cap_F: 100nF  [WCAP-CSGP_0402_L1W0.5H0.5]  (hidden comment: 885012205085R)
C103  Cap_F: 10nF  Rated Voltage (DC): 250V  [WCAP-CSMH_0603_L1.6W0.8H0.8_Reflow]  (hidden comment: 885342206006)
C104  Cap_F: 100nF  [WCAP-CSGP_0402_L1W0.5H0.5]  (hidden comment: 885012205085R)
C105  Cap_F: 10nF  Rated Voltage (DC): 250V  [WCAP-CSMH_0603_L1.6W0.8H0.8_Reflow]  (hidden comment: 885342206006)
C106  Cap_F: 1.5nF  [WCAP-CSGP_0402_L1W0.5H0.5]  (hidden comment: 885012205062)
C107  Cap_F: 1.5nF  [WCAP-CSGP_0402_L1W0.5H0.5]  (hidden comment: 885012205062)
C108  Cap_F: 100nF  [WCAP-CSGP_0402_L1W0.5H0.5]  (hidden comment: 885012205085R)
C109  Cap_F: 10nF  Rated Voltage (DC): 250V  [WCAP-CSMH_0603_L1.6W0.8H0.8_Reflow]  (hidden comment: 885342206006)
C110  Cap_F: 1.5nF  [WCAP-CSGP_0402_L1W0.5H0.5]  (hidden comment: 885012205062)
C111  Cap_F: 1.5nF  [WCAP-CSGP_0402_L1W0.5H0.5]  (hidden comment: 885012205062)
C112  Cap_F: 100nF  [WCAP-CSGP_0402_L1W0.5H0.5]  (hidden comment: 885012205085R)
C113  Cap_F: 10nF  Rated Voltage (DC): 250V  [WCAP-CSMH_0603_L1.6W0.8H0.8_Reflow]  (hidden comment: 885342206006)
C114  Cap_F: 100nF  [WCAP-CSGP_0402_L1W0.5H0.5]  (hidden comment: 885012205085R)
C115  Cap_F: 10nF  Rated Voltage (DC): 250V  [WCAP-CSMH_0603_L1.6W0.8H0.8_Reflow]  (hidden comment: 885342206006)
C116  Cap_F: 1.5nF  [WCAP-CSGP_0402_L1W0.5H0.5]  (hidden comment: 885012205062)
C117  Cap_F: 1.5nF  [WCAP-CSGP_0402_L1W0.5H0.5]  (hidden comment: 885012205062)
C118  Cap_F: 100nF  [WCAP-CSGP_0402_L1W0.5H0.5]  (hidden comment: 885012205085R)
C119  Cap_F: 10nF  Rated Voltage (DC): 250V  [WCAP-CSMH_0603_L1.6W0.8H0.8_Reflow]  (hidden comment: 885342206006)
C120  Cap_F: 1.5nF  [WCAP-CSGP_0402_L1W0.5H0.5]  (hidden comment: 885012205062)
C121  Cap_F: 1.5nF  [WCAP-CSGP_0402_L1W0.5H0.5]  (hidden comment: 885012205062)
C122  Cap_F: 1.5nF  [WCAP-CSGP_0402_L1W0.5H0.5]  (hidden comment: 885012205062)
C123  Cap_F: 10nF  Rated Voltage (DC): 250V  [WCAP-CSMH_0603_L1.6W0.8H0.8_Reflow]  (hidden comment: 885342206006)
C124  885012005057  [WCAP-CSGP_0402_L1W0.5H0.5]  (value not drawn)
C125  Cap_F: 10nF  Rated Voltage (DC): 250V  [WCAP-CSMH_0603_L1.6W0.8H0.8_Reflow]  (hidden comment: 885342206006)
C126  Cap_F: 1.5nF  [WCAP-CSGP_0402_L1W0.5H0.5]  (hidden comment: 885012205062)
C127  Cap_F: 1.5nF  [WCAP-CSGP_0402_L1W0.5H0.5]  (hidden comment: 885012205062)
C128  885012005057  [WCAP-CSGP_0402_L1W0.5H0.5]  (value not drawn)
C129  Cap_F: 10nF  Rated Voltage (DC): 250V  [WCAP-CSMH_0603_L1.6W0.8H0.8_Reflow]  (hidden comment: 885342206006)
C130  Cap_F: 1.5nF  [WCAP-CSGP_0402_L1W0.5H0.5]  (hidden comment: 885012205062)
C131  Cap_F: 1.5nF  [WCAP-CSGP_0402_L1W0.5H0.5]  (hidden comment: 885012205062)
C132  Cap_F: 10nF  Rated Voltage (DC): 250V  [WCAP-CSMH_0603_L1.6W0.8H0.8_Reflow]  (hidden comment: 885342206006)
C133  Cap_F: 10nF  Rated Voltage (DC): 250V  [WCAP-CSMH_0603_L1.6W0.8H0.8_Reflow]  (hidden comment: 885342206006)
C134  Cap_F: 10nF  Rated Voltage (DC): 250V  [WCAP-CSMH_0603_L1.6W0.8H0.8_Reflow]  (hidden comment: 885342206006)
C135  Cap_F: 10nF  Rated Voltage (DC): 250V  [WCAP-CSMH_0603_L1.6W0.8H0.8_Reflow]  (hidden comment: 885342206006)
C136  Cap_F: 1.5nF  [WCAP-CSGP_0402_L1W0.5H0.5]  (hidden comment: 885012205062)
C137  Cap_F: 1.5nF  [WCAP-CSGP_0402_L1W0.5H0.5]  (hidden comment: 885012205062)
C138  Cap_F: 47pF  Case/Size Code: 0402  [WCAP-CSGP_0402_L1W0.5H0.5]  (hidden comment: 885012005059)
C139  Cap_F: 47pF  Case/Size Code: 0402  [WCAP-CSGP_0402_L1W0.5H0.5]  (hidden comment: 885012005059)
C140  Cap_F: 10nF  Rated Voltage (DC): 250V  [WCAP-CSMH_0603_L1.6W0.8H0.8_Reflow]  (hidden comment: 885342206006)
C141  Cap_F: 10nF  Rated Voltage (DC): 250V  [WCAP-CSMH_0603_L1.6W0.8H0.8_Reflow]  (hidden comment: 885342206006)
C142  ValueDisplayed: 0.1uF  [0402]  (hidden comment: GCM155R71H104KE02D)
C143  ValueDisplayed: 0.1uF  [0402]  (hidden comment: GCM155R71H104KE02D)
C144  Cap_F: 1.5nF  [WCAP-CSGP_0402_L1W0.5H0.5]  (hidden comment: 885012205062)
C145  Cap_F: 1.5nF  [WCAP-CSGP_0402_L1W0.5H0.5]  (hidden comment: 885012205062)
C146  Cap_F: 10nF  Rated Voltage (DC): 250V  [WCAP-CSMH_0603_L1.6W0.8H0.8_Reflow]  (hidden comment: 885342206006)
C147  Cap_F: 47pF  Case/Size Code: 0402  [WCAP-CSGP_0402_L1W0.5H0.5]  (hidden comment: 885012005059)
C148  Cap_F: 47pF  Case/Size Code: 0402  [WCAP-CSGP_0402_L1W0.5H0.5]  (hidden comment: 885012005059)
C149  Cap_F: 47pF  Case/Size Code: 0402  [WCAP-CSGP_0402_L1W0.5H0.5]  (hidden comment: 885012005059)
C150  Cap_F: 47pF  Case/Size Code: 0402  [WCAP-CSGP_0402_L1W0.5H0.5]  (hidden comment: 885012005059)
C151  Cap_F: 47pF  Case/Size Code: 0402  [WCAP-CSGP_0402_L1W0.5H0.5]  (hidden comment: 885012005059)
C152  Cap_F: 1.5nF  [WCAP-CSGP_0402_L1W0.5H0.5]  (hidden comment: 885012205062)
C153  Cap_F: 1.5nF  [WCAP-CSGP_0402_L1W0.5H0.5]  (hidden comment: 885012205062)
C154  Cap_F: 47pF  Case/Size Code: 0402  [WCAP-CSGP_0402_L1W0.5H0.5]  (hidden comment: 885012005059)
C155  Capacitance: 100nF  [WCAP-CSGP_0402_L1W0.5H0.5]  (hidden comment: 885012205092)
C156  Cap_F: 1.5nF  [WCAP-CSGP_0402_L1W0.5H0.5]  (hidden comment: 885012205062)
C157  Cap_F: 1.5nF  [WCAP-CSGP_0402_L1W0.5H0.5]  (hidden comment: 885012205062)
C158  VDC_V: 16V  ValueDisplayed: 1.0uF  [FP-GRM155C81C105KE11D_0402-MFG]  (hidden comment: GRM155C81C105KE11D)
C159  VDC_V: 16V  ValueDisplayed: 1.0uF  [FP-GRM155C81C105KE11D_0402-MFG]  (hidden comment: GRM155C81C105KE11D)
C160  ValueDisplayed: 0.1uF  [0402]  (hidden comment: GCM155R71H104KE02D)
C161  ValueDisplayed: 0.1uF  [0402]  (hidden comment: GCM155R71H104KE02D)
C162  Cap_F: 1.5nF  [WCAP-CSGP_0402_L1W0.5H0.5]  (hidden comment: 885012205062)
C163  Cap_F: 1.5nF  [WCAP-CSGP_0402_L1W0.5H0.5]  (hidden comment: 885012205062)
C164  Cap_F: 1.5nF  [WCAP-CSGP_0402_L1W0.5H0.5]  (hidden comment: 885012205062)
D1  VRWM: 120V  [SMA]  (hidden comment: SMAJ120A)
D2  MSP3V3-M3/89A  [FP-MSP3V3-M3/89A_DO-219AD-MFG]
D3  DFLS1200Q-7  [FP-DFLS1200Q-7_PowerDI123-MFG]
D4  Breakdown Voltage: 4.5V  [DYF0002A-MFG]  (hidden comment: TSD03DYFR)
D5  ESD652DBZRQ1  [DBZ0003A-MFG]
D6  ESD652DBZRQ1  [DBZ0003A-MFG]
D7  SMD16PL-TP  [FP-SMD16PL-TP_SOD123FL-MFG]
D8  Breakdown Voltage: 4.5V  [DYF0002A-MFG]  (hidden comment: TSD03DYFR)
DVDD_LED1  value Green  [WL-SMCW_GREEN]  (hidden comment: 150060GS75000)
J1  61301211121  [61301211121]
J2  61301011121  [Wurth_61301011121]
J3  61301011121  [Wurth_61301011121]
J4  141114-214010  [FP-141114-214010_HDR40-MFG]  (parts A,B,C of 3)
J5  141115-214010  [FP-141114-214010_HDR40-MFG]  (parts A,B,C of 3)
J6  PEC03SAAN  [CONN_PEC03SAAN]  (value not drawn)
J7  FTSH-105-01-L-DV-K  [Samtec_FTSH-105-01-x-DV-K]
J8  PRPC010DAAN-RC  [Sullins_xxxC010DAAN]  (value not drawn)
J9  PEC03SAAN  [CONN_PEC03SAAN]  (value not drawn)
J10  PEC03SAAN  [CONN_PEC03SAAN]  (value not drawn)
J11  B2B-PH-K-S(LF)(SN)  [JST_B2B-PH-K-S]
J12  FTSH-103-01-L-DV-K  [FP-FTSH-103-01-F-DV-TR_HDR6-MFG]  (value not drawn)  (parts A,B of 2)
L2  Current Rating: 420mA  Inductance: 100µH  [WE-LQS_4018]  (hidden comment: 74404042101)
LDOIN_LED1  value Green  [WL-SMCW_GREEN]  (hidden comment: 150060GS75000)
NFAULT_LED1  value Red  [WL-SMCW_RED]  (hidden comment: 150060RS75000)
Q1  SSM6L56FE,LM  [FP-SSM6L56FE,LM_SOT563-MFG]  (value not drawn)  (parts A,B of 2)
R1  Value2: 0.125W  ValueDisplayed: 28.0  [0805_HV]  (hidden comment: CRCW080528R0FKEA)
R2  ValueDisplayed: 68  [0805_HV]  (hidden comment: HPCR0805J68R0KT)
R3  ValueDisplayed: 68  [0805_HV]  (hidden comment: HPCR0805J68R0KT)
R4  ValueDisplayed: 68  [0805_HV]  (hidden comment: HPCR0805J68R0KT)
R5  ValueDisplayed: 68  [0805_HV]  (hidden comment: HPCR0805J68R0KT)
R6  Power_W: 750mW  Res_ohm: 62  [FP-CRCW120662R0JNEAHP_1206-MFG]  (hidden comment: CRCW120662R0JNEAHP)
R7  Value2: 0.125W  ValueDisplayed: 51  [0805_HV]  (hidden comment: CRCW080551R0JNEA)
R8  ValueDisplayed: 68  [0805_HV]  (hidden comment: HPCR0805J68R0KT)
R9  ValueDisplayed: 68  [0805_HV]  (hidden comment: HPCR0805J68R0KT)
R10  ValueDisplayed: 68  [0805_HV]  (hidden comment: HPCR0805J68R0KT)
R11  ValueDisplayed: 68  [0805_HV]  (hidden comment: HPCR0805J68R0KT)
R12  ValueDisplayed: 68  [0805_HV]  (hidden comment: HPCR0805J68R0KT)
R13  ValueDisplayed: 68  [0805_HV]  (hidden comment: HPCR0805J68R0KT)
R14  ValueDisplayed: 68  [0805_HV]  (hidden comment: HPCR0805J68R0KT)
R15  ValueDisplayed: 68  [0805_HV]  (hidden comment: HPCR0805J68R0KT)
R16  ValueDisplayed: 68  [0805_HV]  (hidden comment: HPCR0805J68R0KT)
R17  ValueDisplayed: 68  [0805_HV]  (hidden comment: HPCR0805J68R0KT)
R18  ValueDisplayed: 68  [0805_HV]  (hidden comment: HPCR0805J68R0KT)
R19  ValueDisplayed: 68  [0805_HV]  (hidden comment: HPCR0805J68R0KT)
R20  DNP  [0603]
R21  ValueDisplayed: 68  [0805_HV]  (hidden comment: HPCR0805J68R0KT)
R22  ValueDisplayed: 68  [0805_HV]  (hidden comment: HPCR0805J68R0KT)
R23  ValueDisplayed: 68  [0805_HV]  (hidden comment: HPCR0805J68R0KT)
R24  ValueDisplayed: 68  [0805_HV]  (hidden comment: HPCR0805J68R0KT)
R25  ValueDisplayed: 68  [0805_HV]  (hidden comment: HPCR0805J68R0KT)
R26  ValueDisplayed: 68  [0805_HV]  (hidden comment: HPCR0805J68R0KT)
R27  ValueDisplayed: 68  [0805_HV]  (hidden comment: HPCR0805J68R0KT)
R28  ValueDisplayed: 68  [0805_HV]  (hidden comment: HPCR0805J68R0KT)
R29  ValueDisplayed: 68  [0805_HV]  (hidden comment: HPCR0805J68R0KT)
R30  ValueDisplayed: 68  [0805_HV]  (hidden comment: HPCR0805J68R0KT)
R31  ValueDisplayed: 68  [0805_HV]  (hidden comment: HPCR0805J68R0KT)
R32  ValueDisplayed: 68  [0805_HV]  (hidden comment: HPCR0805J68R0KT)
R33  ValueDisplayed: 68  [0805_HV]  (hidden comment: HPCR0805J68R0KT)
R34  ValueDisplayed: 68  [0805_HV]  (hidden comment: HPCR0805J68R0KT)
R35  ValueDisplayed: 68  [0805_HV]  (hidden comment: HPCR0805J68R0KT)
R36  ValueDisplayed: 68  [0805_HV]  (hidden comment: HPCR0805J68R0KT)
R37  ValueDisplayed: 120  [0603]  (hidden comment: RC0603FR-07120RL)
R38  ValueDisplayed: 68  [0805_HV]  (hidden comment: HPCR0805J68R0KT)
R39  ValueDisplayed: 68  [0805_HV]  (hidden comment: HPCR0805J68R0KT)
R40  ValueDisplayed: 68  [0805_HV]  (hidden comment: HPCR0805J68R0KT)
R41  ValueDisplayed: 68  [0805_HV]  (hidden comment: HPCR0805J68R0KT)
R42  ValueDisplayed: 68  [0805_HV]  (hidden comment: HPCR0805J68R0KT)
R43  ValueDisplayed: 68  [0805_HV]  (hidden comment: HPCR0805J68R0KT)
R44  ValueDisplayed: 68  [0805_HV]  (hidden comment: HPCR0805J68R0KT)
R45  ValueDisplayed: 68  [0805_HV]  (hidden comment: HPCR0805J68R0KT)
R46  ValueDisplayed: 68  [0805_HV]  (hidden comment: HPCR0805J68R0KT)
R47  ValueDisplayed: 68  [0805_HV]  (hidden comment: HPCR0805J68R0KT)
R48  ValueDisplayed: 68  [0805_HV]  (hidden comment: HPCR0805J68R0KT)
R49  ValueDisplayed: 68  [0805_HV]  (hidden comment: HPCR0805J68R0KT)
R50  ValueDisplayed: 0  [0603]  (hidden comment: ERJ-3GEY0R00V)
R51  ValueDisplayed: 68  [0805_HV]  (hidden comment: HPCR0805J68R0KT)
R52  ValueDisplayed: 68  [0805_HV]  (hidden comment: HPCR0805J68R0KT)
R53  ValueDisplayed: 68  [0805_HV]  (hidden comment: HPCR0805J68R0KT)
R54  ValueDisplayed: 68  [0805_HV]  (hidden comment: HPCR0805J68R0KT)
R55  Res_ohm: 10  [FP-ERJ-2RKF10R0X_0402-MFG]  (hidden comment: ERJ-2RKF10R0X)
R56  ValueDisplayed: 10.2k  [0402]  (hidden comment: CRCW040210K2FKED)
R57  Res_ohm: 10  [FP-ERJ-2RKF10R0X_0402-MFG]  (hidden comment: ERJ-2RKF10R0X)
R58  ValueDisplayed: 68  [0805_HV]  (hidden comment: HPCR0805J68R0KT)
R59  ValueDisplayed: 68  [0805_HV]  (hidden comment: HPCR0805J68R0KT)
R60  ValueDisplayed: 68  [0805_HV]  (hidden comment: HPCR0805J68R0KT)
R61  ValueDisplayed: 68  [0805_HV]  (hidden comment: HPCR0805J68R0KT)
R62  ValueDisplayed: 68  [0805_HV]  (hidden comment: HPCR0805J68R0KT)
R63  ValueDisplayed: 68  [0805_HV]  (hidden comment: HPCR0805J68R0KT)
R64  ValueDisplayed: 68  [0805_HV]  (hidden comment: HPCR0805J68R0KT)
R65  ValueDisplayed: 68  [0805_HV]  (hidden comment: HPCR0805J68R0KT)
R66  ValueDisplayed: 68  [0805_HV]  (hidden comment: HPCR0805J68R0KT)
R67  ValueDisplayed: 68  [0805_HV]  (hidden comment: HPCR0805J68R0KT)
R68  ValueDisplayed: 68  [0805_HV]  (hidden comment: HPCR0805J68R0KT)
R69  ValueDisplayed: 68  [0805_HV]  (hidden comment: HPCR0805J68R0KT)
R70  ValueDisplayed: 0  [0402]  (hidden comment: ERJ-2GE0R00X)
R71  ValueDisplayed: 0  [0402]  (hidden comment: ERJ-2GE0R00X)
R72  ValueDisplayed: 68  [0805_HV]  (hidden comment: HPCR0805J68R0KT)
R73  ValueDisplayed: 68  [0805_HV]  (hidden comment: HPCR0805J68R0KT)
R74  ValueDisplayed: 68  [0805_HV]  (hidden comment: HPCR0805J68R0KT)
R75  ValueDisplayed: 68  [0805_HV]  (hidden comment: HPCR0805J68R0KT)
R76  ValueDisplayed: 10.2k  [0402]  (hidden comment: CRCW040210K2FKED)
R77  ValueDisplayed: 0  [0402]  (hidden comment: ERJ-2GE0R00X)
R78  ValueDisplayed: 0  [0402]  (hidden comment: ERJ-2GE0R00X)
R79  ValueDisplayed: 0  [0402]  (hidden comment: ERJ-2GE0R00X)
R80  ValueDisplayed: 68  [0805_HV]  (hidden comment: HPCR0805J68R0KT)
R81  ValueDisplayed: 68  [0805_HV]  (hidden comment: HPCR0805J68R0KT)
R82  ValueDisplayed: 68  [0805_HV]  (hidden comment: HPCR0805J68R0KT)
R83  ValueDisplayed: 68  [0805_HV]  (hidden comment: HPCR0805J68R0KT)
R84  ValueDisplayed: 68  [0805_HV]  (hidden comment: HPCR0805J68R0KT)
R85  ValueDisplayed: 68  [0805_HV]  (hidden comment: HPCR0805J68R0KT)
R86  ValueDisplayed: 68  [0805_HV]  (hidden comment: HPCR0805J68R0KT)
R87  ValueDisplayed: 68  [0805_HV]  (hidden comment: HPCR0805J68R0KT)
R88  ValueDisplayed: 68  [0805_HV]  (hidden comment: HPCR0805J68R0KT)
R89  ValueDisplayed: 68  [0805_HV]  (hidden comment: HPCR0805J68R0KT)
R90  ValueDisplayed: 68  [0805_HV]  (hidden comment: HPCR0805J68R0KT)
R91  ValueDisplayed: 68  [0805_HV]  (hidden comment: HPCR0805J68R0KT)
R92  ValueDisplayed: 68  [0805_HV]  (hidden comment: HPCR0805J68R0KT)
R93  ValueDisplayed: 68  [0805_HV]  (hidden comment: HPCR0805J68R0KT)
R94  ValueDisplayed: 68  [0805_HV]  (hidden comment: HPCR0805J68R0KT)
R95  ValueDisplayed: 68  [0805_HV]  (hidden comment: HPCR0805J68R0KT)
R96  ValueDisplayed: 68  [0805_HV]  (hidden comment: HPCR0805J68R0KT)
R97  ValueDisplayed: 68  [0805_HV]  (hidden comment: HPCR0805J68R0KT)
R98  ValueDisplayed: 68  [0805_HV]  (hidden comment: HPCR0805J68R0KT)
R99  ValueDisplayed: 68  [0805_HV]  (hidden comment: HPCR0805J68R0KT)
R100  ValueDisplayed: 68  [0805_HV]  (hidden comment: HPCR0805J68R0KT)
R101  ValueDisplayed: 68  [0805_HV]  (hidden comment: HPCR0805J68R0KT)
R102  ValueDisplayed: 68  [0805_HV]  (hidden comment: HPCR0805J68R0KT)
R103  ValueDisplayed: 68  [0805_HV]  (hidden comment: HPCR0805J68R0KT)
R104  ValueDisplayed: 68  [0805_HV]  (hidden comment: HPCR0805J68R0KT)
R105  ValueDisplayed: 0  [0402]  (hidden comment: ERJ-2GE0R00X)
R107  ValueDisplayed: 68  [0805_HV]  (hidden comment: HPCR0805J68R0KT)
R108  ValueDisplayed: 68  [0805_HV]  (hidden comment: HPCR0805J68R0KT)
R109  ValueDisplayed: 68  [0805_HV]  (hidden comment: HPCR0805J68R0KT)
R110  ValueDisplayed: 68  [0805_HV]  (hidden comment: HPCR0805J68R0KT)
R111  ValueDisplayed: 68  [0805_HV]  (hidden comment: HPCR0805J68R0KT)
R112  ValueDisplayed: 68  [0805_HV]  (hidden comment: HPCR0805J68R0KT)
R113  ValueDisplayed: 68  [0805_HV]  (hidden comment: HPCR0805J68R0KT)
R114  ValueDisplayed: 68  [0805_HV]  (hidden comment: HPCR0805J68R0KT)
R115  ValueDisplayed: 68  [0805_HV]  (hidden comment: HPCR0805J68R0KT)
R116  ValueDisplayed: 68  [0805_HV]  (hidden comment: HPCR0805J68R0KT)
R117  ValueDisplayed: 68  [0805_HV]  (hidden comment: HPCR0805J68R0KT)
R118  ValueDisplayed: 68  [0805_HV]  (hidden comment: HPCR0805J68R0KT)
R119  ValueDisplayed: 68  [0805_HV]  (hidden comment: HPCR0805J68R0KT)
R120  ValueDisplayed: 68  [0805_HV]  (hidden comment: HPCR0805J68R0KT)
R121  ValueDisplayed: 68  [0805_HV]  (hidden comment: HPCR0805J68R0KT)
R122  ValueDisplayed: 68  [0805_HV]  (hidden comment: HPCR0805J68R0KT)
R123  ValueDisplayed: 68  [0805_HV]  (hidden comment: HPCR0805J68R0KT)
R124  ValueDisplayed: 68  [0805_HV]  (hidden comment: HPCR0805J68R0KT)
R125  ValueDisplayed: 68  [0805_HV]  (hidden comment: HPCR0805J68R0KT)
R126  ValueDisplayed: 4.70k  [0402]  (hidden comment: RC0402FR-074K7L)
R127  ValueDisplayed: 1.0k  [0603]  (hidden comment: ESR03EZPJ102)
R128  ValueDisplayed: 1.0k  [0603]  (hidden comment: ESR03EZPJ102)
R129  ValueDisplayed: 4.70k  [0402]  (hidden comment: RC0402FR-074K7L)
R130  ValueDisplayed: 1.0k  [0603]  (hidden comment: ESR03EZPJ102)
R131  ValueDisplayed: 10.0k  [0402]  (hidden comment: CRCW040210K0FKED)
R132  ValueDisplayed: 10.0k  [0402]  (hidden comment: CRCW040210K0FKED)
R133  ValueDisplayed: 10.0k  [0402]  (hidden comment: CRCW040210K0FKED)
R134  ValueDisplayed: 10.0k  [0402]  (hidden comment: CRCW040210K0FKED)
R135  ValueDisplayed: 10.0k  [0402]  (hidden comment: CRCW040210K0FKED)
R136  ValueDisplayed: 10.0k  [0402]  (hidden comment: CRCW040210K0FKED)
R137  ValueDisplayed: 10.0k  [0402]  (hidden comment: CRCW040210K0FKED)
R138  ValueDisplayed: 10.0k  [0402]  (hidden comment: CRCW040210K0FKED)
R140  ValueDisplayed: 1.0k  [0402]  (hidden comment: CRCW04021K00JNED)
R141  ValueDisplayed: 1.0k  [0402]  (hidden comment: CRCW04021K00JNED)
R143  ValueDisplayed: 1.0k  [0402]  (hidden comment: CRCW04021K00JNED)
R144  ValueDisplayed: 100k  [0402]  (hidden comment: AC0402FR-07100KL)
R146  ValueDisplayed: 1.0k  [0402]  (hidden comment: CRCW04021K00JNED)
R147  ValueDisplayed: 1.0k  [0402]  (hidden comment: CRCW04021K00JNED)
R149  ValueDisplayed: 1.0k  [0402]  (hidden comment: CRCW04021K00JNED)
R150  ValueDisplayed: 100k  [0402]  (hidden comment: AC0402FR-07100KL)
R152  ValueDisplayed: 1.0k  [0402]  (hidden comment: CRCW04021K00JNED)
R153  ValueDisplayed: 4.70k  [0402]  (hidden comment: RC0402FR-074K7L)
R155  ValueDisplayed: 100k  [0402]  (hidden comment: AC0402FR-07100KL)
R156  ValueDisplayed: 1.0k  [0402]  (hidden comment: CRCW04021K00JNED)
R157  ValueDisplayed: 100k  [0402]  (hidden comment: AC0402FR-07100KL)
R159  ValueDisplayed: 1.0k  [0402]  (hidden comment: CRCW04021K00JNED)
R160  ValueDisplayed: 1.0k  [0402]  (hidden comment: CRCW04021K00JNED)
R162  ValueDisplayed: 100k  [0402]  (hidden comment: AC0402FR-07100KL)
R163  ValueDisplayed: 1.0k  [0402]  (hidden comment: CRCW04021K00JNED)
R164  ValueDisplayed: 100k  [0402]  (hidden comment: AC0402FR-07100KL)
R165  ValueDisplayed: 100k  [0402]  (hidden comment: AC0402FR-07100KL)
R166  ValueDisplayed: 100k  [0402]  (hidden comment: AC0402FR-07100KL)
R167  ValueDisplayed: 100k  [0402]  (hidden comment: AC0402FR-07100KL)
R168  ValueDisplayed: 10.0k  [0402]  (hidden comment: CRCW040210K0FKED)
R169  ValueDisplayed: 10.0k  [0402]  (hidden comment: CRCW040210K0FKED)
R170  ValueDisplayed: 10.0k  [0402]  (hidden comment: CRCW040210K0FKED)
R171  ValueDisplayed: 10.0k  [0402]  (hidden comment: CRCW040210K0FKED)
R172  ValueDisplayed: 10.0k  [0402]  (hidden comment: CRCW040210K0FKED)
R173  ValueDisplayed: 10.0k  [0402]  (hidden comment: CRCW040210K0FKED)
R174  ValueDisplayed: 10.0k  [0402]  (hidden comment: CRCW040210K0FKED)
R175  ValueDisplayed: 10.0k  [0402]  (hidden comment: CRCW040210K0FKED)
R176  ValueDisplayed: 1.0k  [0402]  (hidden comment: CRCW04021K00JNED)
R177  ValueDisplayed: 1.0k  [0402]  (hidden comment: CRCW04021K00JNED)
R178  ValueDisplayed: 1.0k  [0402]  (hidden comment: CRCW04021K00JNED)
R179  ValueDisplayed: 100k  [0402]  (hidden comment: AC0402FR-07100KL)
R180  ValueDisplayed: 1.0k  [0402]  (hidden comment: CRCW04021K00JNED)
R181  ValueDisplayed: 1.0k  [0402]  (hidden comment: CRCW04021K00JNED)
R182  ValueDisplayed: 1.0k  [0402]  (hidden comment: CRCW04021K00JNED)
R183  ValueDisplayed: 100k  [0402]  (hidden comment: AC0402FR-07100KL)
R184  ValueDisplayed: 1.0k  [0402]  (hidden comment: CRCW04021K00JNED)
R185  ValueDisplayed: 4.70k  [0402]  (hidden comment: RC0402FR-074K7L)
R186  ValueDisplayed: 1.0k  [0402]  (hidden comment: CRCW04021K00JNED)
R187  ValueDisplayed: 100k  [0402]  (hidden comment: AC0402FR-07100KL)
R188  ValueDisplayed: 1.0k  [0402]  (hidden comment: CRCW04021K00JNED)
R189  ValueDisplayed: 1.0k  [0402]  (hidden comment: CRCW04021K00JNED)
R190  ValueDisplayed: 1.0k  [0402]  (hidden comment: CRCW04021K00JNED)
R191  ValueDisplayed: 100k  [0402]  (hidden comment: AC0402FR-07100KL)
R192  ValueDisplayed: 1.00k  [0402]  (hidden comment: CRCW04021K00FKED)
R193  ValueDisplayed: 10.0k  [0402]  (hidden comment: CRCW040210K0FKED)
R194  ValueDisplayed: 1.00k  [0402]  (hidden comment: CRCW04021K00FKED)
R195  ValueDisplayed: 1.00k  [0402]  (hidden comment: CRCW04021K00FKED)
R196  ValueDisplayed: 1.0k  [0402]  (hidden comment: CRCW04021K00JNED)
R197  ValueDisplayed: 1.00k  [0402]  (hidden comment: CRCW04021K00FKED)
R198  ValueDisplayed: 1.00k  [0402]  (hidden comment: CRCW04021K00FKED)
R199  ValueDisplayed: 1.00k  [0402]  (hidden comment: CRCW04021K00FKED)
R200  ValueDisplayed: 1.00k  [0402]  (hidden comment: CRCW04021K00FKED)
R201  ValueDisplayed: 1.00k  [0402]  (hidden comment: CRCW04021K00FKED)
R202  ValueDisplayed: 1.00k  [0402]  (hidden comment: CRCW04021K00FKED)
R203  ValueDisplayed: 1.00k  [0402]  (hidden comment: CRCW04021K00FKED)
R204  ValueDisplayed: 1.00k  [0402]  (hidden comment: CRCW04021K00FKED)
R205  ValueDisplayed: 1.00k  [0402]  (hidden comment: CRCW04021K00FKED)
R206  ValueDisplayed: 1.00k  [0402]  (hidden comment: CRCW04021K00FKED)
R207  ValueDisplayed: 1.00k  [0402]  (hidden comment: CRCW04021K00FKED)
R208  ValueDisplayed: 1.00k  [0402]  (hidden comment: CRCW04021K00FKED)
R209  ValueDisplayed: 0  [0402]  (hidden comment: ERJ-2GE0R00X)
R210  ValueDisplayed: 10  [0805_HV]  (hidden comment: ERJ-6GEYJ100V)
R211  ValueDisplayed: 0  [0402]  (hidden comment: ERJ-2GE0R00X)
R212  ValueDisplayed: 10  [0805_HV]  (hidden comment: ERJ-6GEYJ100V)
R213  ValueDisplayed: 1.00k  [0402]  (hidden comment: CRCW04021K00FKED)
R214  ValueDisplayed: 1.00k  [0402]  (hidden comment: CRCW04021K00FKED)
R215  ValueDisplayed: 80.6  [1206]  (hidden comment: ERJ-8ENF80R6V)
R216  ValueDisplayed: 1.00k  [0402]  (hidden comment: CRCW04021K00FKED)
R217  ValueDisplayed: 1.00k  [0402]  (hidden comment: CRCW04021K00FKED)
R218  ValueDisplayed: 80.6  [1206]  (hidden comment: ERJ-8ENF80R6V)
R219  ValueDisplayed: 1.00k  [0402]  (hidden comment: CRCW04021K00FKED)
R220  ValueDisplayed: 1.00k  [0402]  (hidden comment: CRCW04021K00FKED)
R221  ValueDisplayed: 80.6  [1206]  (hidden comment: ERJ-8ENF80R6V)
R222  ValueDisplayed: 80.6  [1206]  (hidden comment: ERJ-8ENF80R6V)
R223  ValueDisplayed: 1.00k  [0402]  (hidden comment: CRCW04021K00FKED)
R224  ValueDisplayed: 1.00k  [0402]  (hidden comment: CRCW04021K00FKED)
R225  ValueDisplayed: 10  [0805_HV]  (hidden comment: ERJ-6GEYJ100V)
R226  ValueDisplayed: 0  [0402]  (hidden comment: ERJ-2GE0R00X)
R227  ValueDisplayed: 0  [0402]  (hidden comment: ERJ-2GE0R00X)
R228  ValueDisplayed: 10  [0805_HV]  (hidden comment: ERJ-6GEYJ100V)
R229  ValueDisplayed: 1.00k  [0402]  (hidden comment: CRCW04021K00FKED)
R230  ValueDisplayed: 1.00k  [0402]  (hidden comment: CRCW04021K00FKED)
R231  ValueDisplayed: 1.00k  [0402]  (hidden comment: CRCW04021K00FKED)
R232  ValueDisplayed: 1.00k  [0402]  (hidden comment: CRCW04021K00FKED)
R233  ValueDisplayed: 100k  [0402]  (hidden comment: AC0402FR-07100KL)
R234  ValueDisplayed: 100k  [0402]  (hidden comment: AC0402FR-07100KL)
R235  ValueDisplayed: 100k  [0402]  (hidden comment: AC0402FR-07100KL)
R236  ValueDisplayed: 100k  [0402]  (hidden comment: AC0402FR-07100KL)
RT1  value 10k  [DYA0002A-MFG]  (hidden comment: TMP6131DYAT)
TSREF_LED1  value Green  [WL-SMCW_GREEN]  (hidden comment: 150060GS75000)
U1  BQ79826ZQPZSRQ1  [PZQ0100A-MFG]
U2  TMUX1308PWR  [PW0016A-MFG]
U3  TMUX1308PWR  [PW0016A-MFG]
U4  TLV74315PDBVR  [DBV0005A_N]
U5  SN74LXC1T14DCKR  [DCK0005A-MFG]
Y2  830055663  [FP-830055663_SMT_CRYSTAL_5MM0_3MM2-MFG]  (value not drawn)

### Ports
CELL0 (bidir), CELL1 (bidir), CELL2 (bidir), CELL3 (bidir), CELL4 (bidir), CELL5 (bidir), CELL6 (bidir), CELL7 (bidir), CELL8 (bidir), CELL9 (bidir), CELL10 (bidir), CELL11 (bidir), CELL12 (bidir), CELL13 (bidir), CELL14 (bidir), CELL15 (bidir), CELL16 (bidir), CELL17 (bidir), CELL18 (bidir), CELL19 (bidir), CELL20 (bidir), CELL21 (bidir), CELL22 (bidir), CELL23 (bidir), CELL24 (bidir), CELL25 (bidir), CELL26 (bidir), COMMH_N_OPT (bidir), COMMH_P_OPT (bidir), COMML_N_OPT (bidir), COMML_P_OPT (bidir), GND, PWR (bidir), TS1 (bidir), TS2 (bidir), TS3 (bidir), TS4 (bidir), TS5 (bidir), TS6 (bidir), TS7 (bidir), TS8 (bidir), TS9 (bidir), TS10 (bidir), TS11 (bidir), TS12 (bidir), TS13 (bidir), TS14 (bidir), TS15 (bidir)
